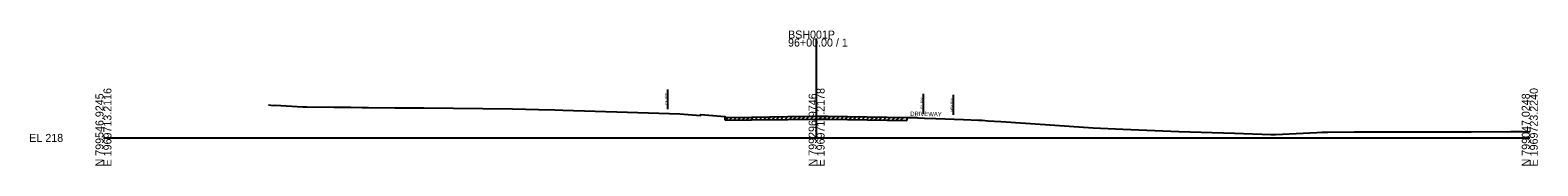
# Model space of a CAD drawing. Extents: x 1979833 to 1982361, y 790388 to 810009.
# Drawn here: x 1981583 to 1982111, y 797388 to 797435 of the extents above; entities that cross this region are included whole.
import ezdxf

# ---------------------------------------------------------------- set-up
doc = ezdxf.new("R2010")
doc.units = 0
for name, color, linetype in [('Default', 7, 'Continuous'), ('RD_GPK_XS_Cell', 7, 'Continuous'), ('RD_XS_ExGround', 7, 'Continuous'), ('RD_XS_ExPaveRet', 7, 'Continuous'), ('RD_XS_ExRW', 7, 'Continuous'), ('RD_XS_NewRW', 7, 'Continuous'), ('RD_XS_Pave', 7, 'Continuous')]:
    doc.layers.add(name, color=color, linetype=linetype)

msp = doc.modelspace()

# ---------------------------------------------------------------- linework, layer by layer
at = {"layer": 'RD_GPK_XS_Cell'}
for p, q in [((1981858.57, 797397.73), (1981858.57, 797432.55)), ((1981608.57, 797397.73), (1981858.57, 797397.73)), ((1981858.57, 797397.73), (1982108.57, 797397.73))]:
    msp.add_line(p, q, dxfattribs=at)
at = {"layer": 'RD_XS_ExGround'}
msp.add_lwpolyline([(1981666.4, 797409.34), (1981668.14, 797409.14), (1981668.82, 797409.2), (1981678.42, 797408.62), (1981679.83, 797408.59), (1981689.43, 797408.54), (1981695.28, 797408.5), (1981699.21, 797408.44), (1981701.45, 797408.4), (1981710.7, 797408.27), (1981720.84, 797408.26), (1981751.95, 797407.88), (1981761.05, 797407.67), (1981766.8, 797407.53), (1981769.63, 797407.41), (1981792.28, 797406.69), (1981810.6, 797406.13), (1981817.85, 797405.6), (1981817.95, 797405.9), (1981825.04, 797405.37), (1981826.41, 797405.22), (1981826.51, 797404.92), (1981835.78, 797405.05), (1981848.54, 797405.22), (1981857.86, 797405.34), (1981858.57, 797405.34), (1981862.48, 797405.29), (1981890.24, 797404.86), (1981890.97, 797404.87), (1981891.93, 797404.88), (1981893.11, 797404.89), (1981893.67, 797404.83), (1981894.09, 797404.78), (1981896.43, 797404.7), (1981900.41, 797404.5), (1981910.03, 797404.21), (1981915.31, 797403.94), (1981915.8, 797403.92), (1981916.24, 797403.9), (1981916.57, 797403.89), (1981918.57, 797403.76), (1981923.1, 797403.44), (1981938.75, 797402.39), (1981955.56, 797401.21), (1981965.93, 797400.83), (1981985.57, 797399.92), (1982005.08, 797399.33), (1982017.8, 797398.87), (1982019.43, 797398.92), (1982033.94, 797399.6), (1982035.68, 797399.68), (1982036.52, 797399.7), (1982037.73, 797399.7), (1982047, 797399.85), (1982059.5, 797399.87), (1982079.9, 797399.91), (1982088.08, 797399.82), (1982101.98, 797399.92), (1982106.13, 797399.93), (1982108.57, 797399.91)], dxfattribs=at)
at = {"layer": 'RD_XS_ExPaveRet'}
for p, q in [((1981826.51, 797403.92), (1981827.52, 797404.93)), ((1981826.51, 797403.92), (1981826.51, 797404.92)), ((1981826.51, 797403.92), (1981835.78, 797404.05)), ((1981828.01, 797403.94), (1981829.02, 797404.95)), ((1981829.51, 797403.96), (1981830.52, 797404.97)), ((1981831.01, 797403.98), (1981832.02, 797404.99)), ((1981832.51, 797404), (1981833.52, 797405.01)), ((1981834.01, 797404.02), (1981835.02, 797405.04)), ((1981835.51, 797404.04), (1981836.52, 797405.06)), ((1981835.78, 797404.05), (1981848.54, 797404.22)), ((1981837.01, 797404.06), (1981838.02, 797405.08)), ((1981838.51, 797404.08), (1981839.52, 797405.1)), ((1981840.01, 797404.1), (1981841.02, 797405.12)), ((1981841.51, 797404.13), (1981842.52, 797405.14)), ((1981843.01, 797404.15), (1981844.02, 797405.16)), ((1981844.51, 797404.17), (1981845.52, 797405.18)), ((1981846.01, 797404.19), (1981847.02, 797405.2)), ((1981847.51, 797404.21), (1981848.52, 797405.22)), ((1981848.54, 797404.22), (1981857.86, 797404.34)), ((1981849.01, 797404.23), (1981850.02, 797405.24)), ((1981850.51, 797404.25), (1981851.52, 797405.26)), ((1981852.01, 797404.27), (1981853.02, 797405.28)), ((1981853.51, 797404.29), (1981854.52, 797405.3)), ((1981855.01, 797404.31), (1981856.02, 797405.32)), ((1981856.51, 797404.33), (1981857.52, 797405.34)), ((1981857.86, 797404.34), (1981858.57, 797404.34)), ((1981858.01, 797404.34), (1981858.99, 797405.33)), ((1981858.57, 797404.34), (1981862.48, 797404.29)), ((1981859.51, 797404.32), (1981860.49, 797405.31)), ((1981861.01, 797404.31), (1981861.99, 797405.3)), ((1981862.48, 797404.29), (1981890.24, 797403.86)), ((1981862.51, 797404.29), (1981863.49, 797405.27)), ((1981864.01, 797404.27), (1981864.99, 797405.25)), ((1981865.51, 797404.24), (1981866.49, 797405.23)), ((1981867.01, 797404.22), (1981867.99, 797405.2)), ((1981868.51, 797404.2), (1981869.49, 797405.18)), ((1981870.01, 797404.17), (1981870.99, 797405.16)), ((1981871.51, 797404.15), (1981872.49, 797405.14)), ((1981873.01, 797404.13), (1981873.99, 797405.11)), ((1981874.51, 797404.11), (1981875.49, 797405.09)), ((1981876.01, 797404.08), (1981876.99, 797405.07)), ((1981877.51, 797404.06), (1981878.49, 797405.04)), ((1981879.01, 797404.04), (1981879.99, 797405.02)), ((1981880.51, 797404.01), (1981881.49, 797405)), ((1981882.01, 797403.99), (1981882.99, 797404.98)), ((1981883.51, 797403.97), (1981884.49, 797404.95)), ((1981885.01, 797403.94), (1981885.99, 797404.93)), ((1981886.51, 797403.92), (1981887.49, 797404.91)), ((1981888.01, 797403.9), (1981888.99, 797404.88)), ((1981890.24, 797404.86), (1981890.24, 797403.86))]:
    msp.add_line(p, q, dxfattribs=at)
at = {"layer": 'RD_XS_ExRW'}
for p, q in [((1981806.37, 797407.75), (1981806.37, 797414.75)), ((1981896.09, 797406.21), (1981896.09, 797413.21))]:
    msp.add_line(p, q, dxfattribs=at)
at = {"layer": 'RD_XS_NewRW'}
msp.add_line((1981906.57, 797405.81), (1981906.57, 797412.81), dxfattribs=at)

# ---------------------------------------------------------------- texts
at = {"layer": 'Default'}
msp.add_text('-', height=0.0001, dxfattribs=at).set_placement((1981608.57, 797397.73))
at = {"layer": 'RD_GPK_XS_Cell'}
for s, p in [('BSH001P', (1981848.57, 797432.55)), ('96+00.00 / 1', (1981848.57, 797429.75)), ('EL 218', (1981582.57, 797396.33))]:
    msp.add_text(s, height=2.8, dxfattribs=at).set_placement(p)
for s, p in [('N 799546.9245', (1981608.57, 797387.73)), ('E 1969713.2116', (1981611.37, 797387.73)), ('N 799296.9746', (1981858.57, 797387.73)), ('E 1969718.2178', (1981861.37, 797387.73)), ('N 799047.0248', (1982108.57, 797387.73)), ('E 1969723.2240', (1982111.37, 797387.73))]:
    msp.add_text(s, height=2.8, rotation=90, dxfattribs=at).set_placement(p)
at = {"layer": 'RD_XS_ExRW'}
for p in [(1981806.12, 797409.44), (1981895.84, 797407.89)]:
    msp.add_text('EX. R/W ', height=0.75, rotation=90, dxfattribs=at).set_placement(p)
at = {"layer": 'RD_XS_NewRW'}
msp.add_text('NEW R/W ', height=0.75, rotation=90, dxfattribs=at).set_placement((1981906.32, 797406.95))
at = {"layer": 'RD_XS_Pave'}
msp.add_text('DRIVEWAY', height=1.5, rotation=359.1246, dxfattribs=at).set_placement((1981891.38, 797405.45))

doc.saveas('drawing.dxf')
